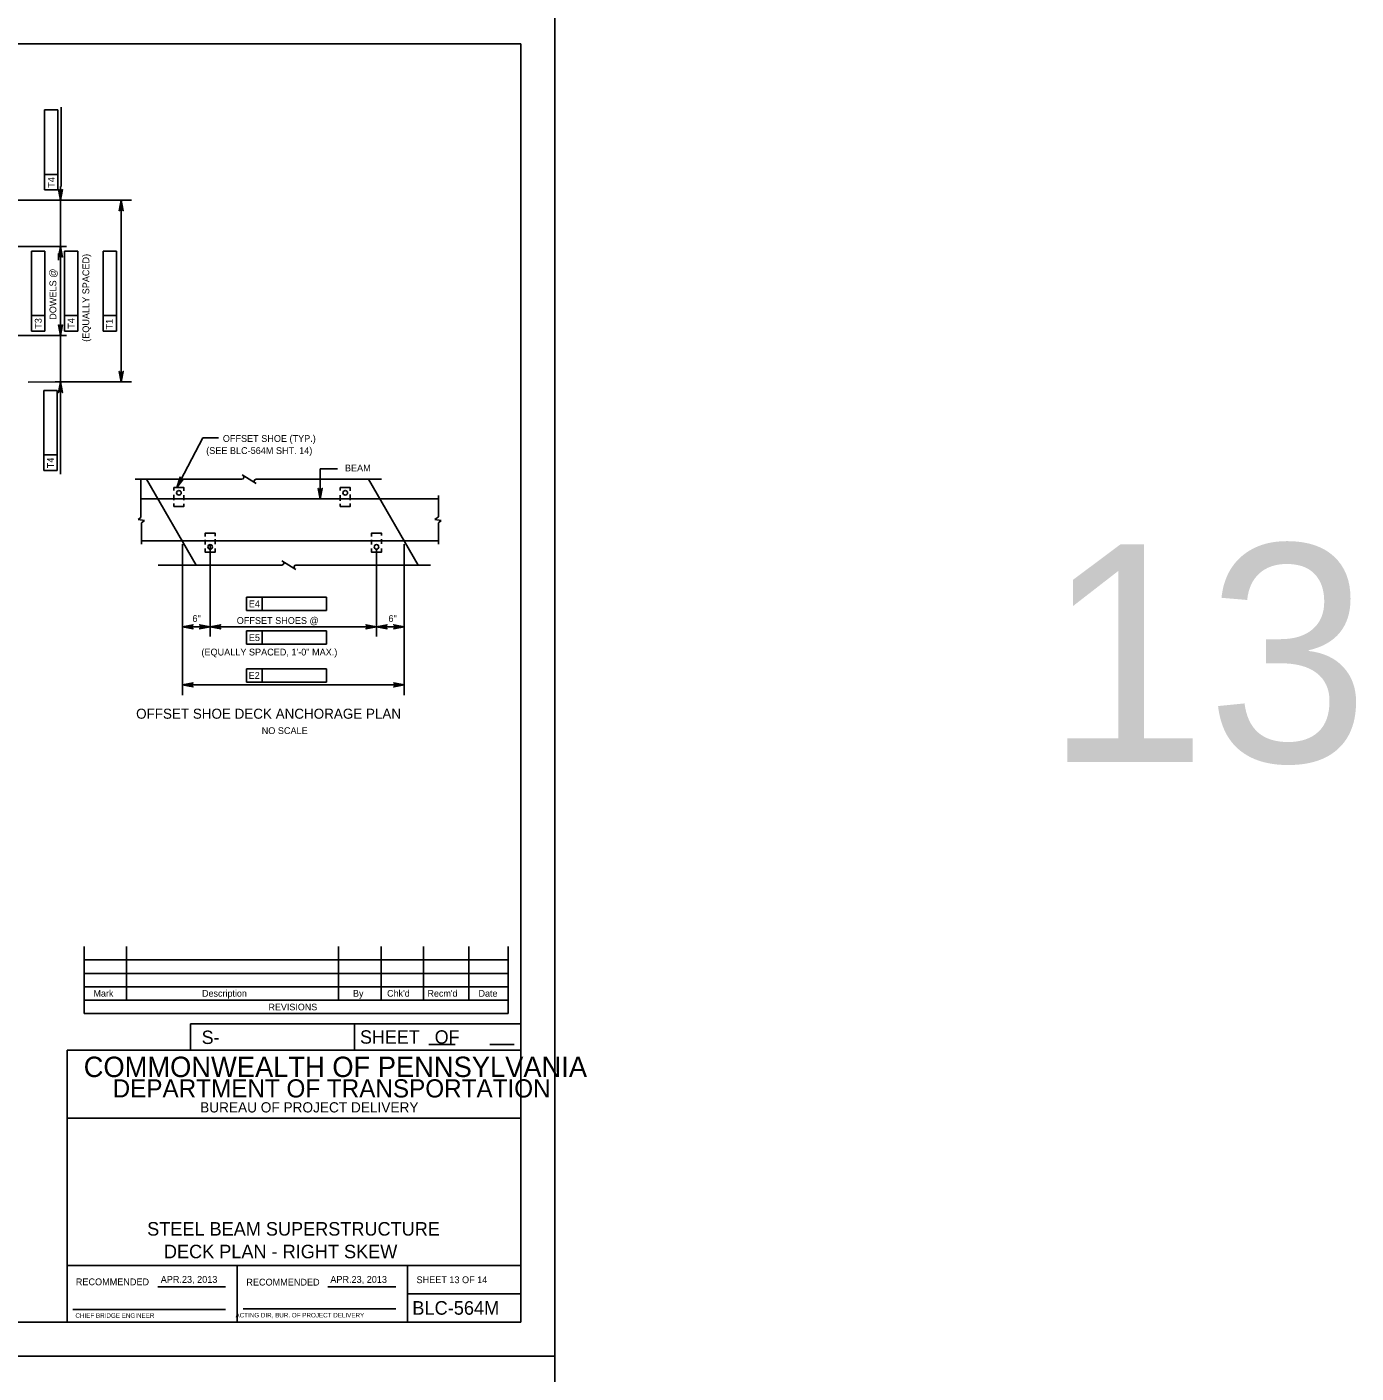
# Model space of a CAD drawing. Extents: x 638175 to 640495, y 294277 to 298435.
# Drawn here: x 639885 to 640471, y 294864 to 295458 of the extents above; entities that cross this region are included whole.
import ezdxf

# ---------------------------------------------------------------- set-up
doc = ezdxf.new("R2010")
doc.units = 0
for name, color, linetype in [('1', 7, 'Continuous'), ('2', 7, 'Continuous'), ('3', 7, 'Continuous'), ('4', 7, 'Continuous'), ('53', 7, 'Continuous'), ('PLT-BNDY', 7, 'Continuous')]:
    doc.layers.add(name, color=color, linetype=linetype)

msp = doc.modelspace()

# ---------------------------------------------------------------- linework, layer by layer
at = {"layer": '2'}
for p, q in [((639316.46, 295450.46), (640102.46, 295450.46)), ((640102.46, 295450.46), (640102.46, 294886.46)), ((639937.34, 295258.4), (639959.24, 295220.5)), ((640035.38, 295258.4), (640057.29, 295220.5)), ((639909.92, 295052.15), (639909.92, 295022.62)), ((639928.62, 295052.15), (639928.62, 295028.53)), ((640022.13, 295052.15), (640022.13, 295028.53)), ((640040.83, 295052.15), (640040.83, 295028.53)), ((640059.53, 295052.15), (640059.53, 295028.53)), ((640079.59, 295052.15), (640079.59, 295028.53)), ((640096.94, 295052.15), (640096.94, 295022.62)), ((640096.94, 295046.24), (639909.92, 295046.24)), ((640096.94, 295040.34), (639909.92, 295040.34)), ((640096.94, 295034.43), (639909.92, 295034.43)), ((640096.94, 295028.53), (639909.92, 295028.53)), ((640096.94, 295022.62), (639909.92, 295022.62)), ((640102.46, 295018.11), (639956.78, 295018.11)), ((639956.78, 295018.11), (639956.78, 295006.46)), ((640029.09, 295018.11), (640029.09, 295006.46)), ((640102.46, 295006.46), (639902.46, 295006.46)), ((639902.46, 295006.46), (639902.46, 294886.46)), ((640061.95, 295009), (640073.6, 295009)), ((640088.83, 295009), (640099.56, 295009)), ((640102.46, 294976.46), (639902.46, 294976.46)), ((640102.46, 294911.46), (639902.46, 294911.46)), ((639977.46, 294886.46), (639977.46, 294911.46)), ((640052.46, 294911.46), (640052.46, 294886.46)), ((639942.42, 294901.96), (639972.19, 294901.96)), ((640017.42, 294901.96), (640047.33, 294901.96)), ((640052.46, 294898.96), (640102.46, 294898.96)), ((639904.96, 294891.96), (639972.19, 294891.96)), ((639980.08, 294892.33), (640047.33, 294892.33)), ((640102.46, 294886.46), (639316.46, 294886.46))]:
    msp.add_line(p, q, dxfattribs=at)
at = {"layer": '3'}
for p, q in [((639720.78, 295361.01), (639902.09, 295361.04)), ((639741.66, 295321.77), (639902.09, 295321.8)), ((639962.21, 295276.64), (639969.2, 295276.64)), ((639979.57, 295260.33), (639985.73, 295256.46)), ((640014.03, 295263), (640021.57, 295263)), ((639979.5, 295258.4), (639932.35, 295258.4)), ((639934.87, 295241.52), (639934.87, 295258.34)), ((640041.04, 295258.4), (639985.71, 295258.4)), ((639934.87, 295249.67), (640066.17, 295249.67)), ((640066.17, 295241.8), (640066.17, 295251.17)), ((640064.63, 295240.61), (640066.17, 295241.8)), ((639933.7, 295240.61), (639934.87, 295241.52)), ((639936.46, 295240.18), (639933.7, 295240.61)), ((639935.24, 295239.09), (639936.46, 295240.18)), ((639935.24, 295229.67), (639935.24, 295239.09)), ((640067.39, 295240.18), (640064.63, 295240.61)), ((640066.17, 295239.09), (640067.39, 295240.18)), ((640066.17, 295229.67), (640066.17, 295239.09)), ((640066.17, 295231.21), (639935.24, 295231.21)), ((639953.26, 295229.73), (639953.26, 295189.02)), ((639965.49, 295229.73), (639965.49, 295189.02)), ((640038.86, 295227.65), (640038.86, 295189.02)), ((640051.09, 295229.73), (640051.09, 295189.02)), ((639942.57, 295220.5), (639997.06, 295220.5)), ((639997.13, 295222.43), (640003.29, 295218.56)), ((640003.27, 295220.5), (640062.64, 295220.5)), ((639968.32, 295193.27), (640036.03, 295193.27))]:
    msp.add_line(p, q, dxfattribs=at)
for points in [[(639953.93, 295253.27), (639953.93, 295254.66), (639949.47, 295254.66), (639949.47, 295253.34)], [(639950.85, 295254.78), (639952.22, 295259.32), (639952.28, 295258.89), (639952.47, 295258.58), (639952.72, 295258.39), (639953.02, 295258.29), (639953.39, 295258.31), (639953.77, 295258.52), (639950.85, 295254.78), (639953.39, 295258.31), (639953.02, 295258.29), (639950.85, 295254.78), (639952.72, 295258.39), (639952.47, 295258.58), (639950.85, 295254.78), (639952.28, 295258.89)], [(640014.02, 295249.67), (640013.15, 295254.33), (640013.4, 295253.97), (640013.71, 295253.78), (640014.02, 295253.73), (640014.34, 295253.78), (640014.65, 295253.97), (640014.9, 295254.33), (640014.02, 295249.67), (640014.65, 295253.97), (640014.34, 295253.78), (640014.02, 295249.67), (640014.02, 295253.73), (640013.71, 295253.78), (640014.02, 295249.67), (640013.4, 295253.97)], [(640022.82, 295253.34), (640022.82, 295254.66), (640027.29, 295254.66), (640027.29, 295253.27)], [(639949.47, 295251.51), (639949.47, 295249.07)], [(639953.93, 295249.07), (639953.93, 295251.28)], [(640022.82, 295248.84), (640022.82, 295251.28)], [(640027.29, 295251.59), (640027.29, 295249.14)], [(639949.47, 295247.61), (639949.47, 295246.35), (639953.93, 295246.35), (639953.93, 295247.46)], [(640027.29, 295247.61), (640027.29, 295246.35), (640022.82, 295246.35), (640022.82, 295247.46)], [(639963.25, 295233.09), (639963.25, 295234.53), (639967.72, 295234.53), (639967.72, 295233.32)], [(639963.25, 295229.5), (639963.25, 295231.64)], [(639967.72, 295231.95), (639967.72, 295229.65)], [(640041.08, 295233.48), (640041.08, 295234.53), (640036.61, 295234.53), (640036.61, 295233.17)], [(640036.61, 295231.64), (640036.61, 295229.5)], [(640041.08, 295229.81), (640041.08, 295231.87)], [(639967.72, 295227.82), (639967.72, 295226.21), (639963.25, 295226.21), (639963.25, 295227.82)], [(640036.61, 295227.82), (640036.61, 295226.21), (640041.08, 295226.21), (640041.08, 295227.82)], [(639953.26, 295193.27), (639957.92, 295194.14), (639957.56, 295193.89), (639957.38, 295193.58), (639957.32, 295193.27), (639957.38, 295192.96), (639957.56, 295192.64), (639957.92, 295192.4), (639953.26, 295193.27), (639957.56, 295192.64), (639957.38, 295192.96), (639953.26, 295193.27), (639957.32, 295193.27), (639957.38, 295193.58), (639953.26, 295193.27), (639957.56, 295193.89)], [(639965.49, 295193.27), (639960.83, 295192.4), (639961.19, 295192.64), (639961.37, 295192.96), (639961.43, 295193.27), (639961.37, 295193.58), (639961.19, 295193.89), (639960.83, 295194.14), (639965.49, 295193.27), (639961.19, 295193.89), (639961.37, 295193.58), (639965.49, 295193.27), (639961.43, 295193.27), (639961.37, 295192.96), (639965.49, 295193.27), (639961.19, 295192.64)], [(639965.49, 295193.27), (639970.15, 295194.14), (639969.79, 295193.89), (639969.61, 295193.58), (639969.55, 295193.27), (639969.61, 295192.96), (639969.79, 295192.64), (639970.15, 295192.4), (639965.49, 295193.27), (639969.79, 295192.64), (639969.61, 295192.96), (639965.49, 295193.27), (639969.55, 295193.27), (639969.61, 295193.58), (639965.49, 295193.27), (639969.79, 295193.89)], [(640038.86, 295193.27), (640034.2, 295192.4), (640034.56, 295192.64), (640034.75, 295192.96), (640034.8, 295193.27), (640034.75, 295193.58), (640034.56, 295193.89), (640034.2, 295194.14), (640038.86, 295193.27), (640034.56, 295193.89), (640034.75, 295193.58), (640038.86, 295193.27), (640034.8, 295193.27), (640034.75, 295192.96), (640038.86, 295193.27), (640034.56, 295192.64)], [(640038.86, 295193.27), (640043.52, 295194.14), (640043.17, 295193.89), (640042.98, 295193.58), (640042.93, 295193.27), (640042.98, 295192.96), (640043.17, 295192.64), (640043.52, 295192.4), (640038.86, 295193.27), (640043.17, 295192.64), (640042.98, 295192.96), (640038.86, 295193.27), (640042.93, 295193.27), (640042.98, 295193.58), (640038.86, 295193.27), (640043.17, 295193.89)], [(640051.09, 295193.27), (640046.43, 295192.4), (640046.79, 295192.64), (640046.98, 295192.96), (640047.03, 295193.27), (640046.98, 295193.58), (640046.79, 295193.89), (640046.43, 295194.14), (640051.09, 295193.27), (640046.79, 295193.89), (640046.98, 295193.58), (640051.09, 295193.27), (640047.03, 295193.27), (640046.98, 295192.96), (640051.09, 295193.27), (640046.79, 295192.64)], [(639953.26, 295167.61), (639957.92, 295168.48), (639957.56, 295168.23), (639957.38, 295167.92), (639957.32, 295167.61), (639957.38, 295167.3), (639957.56, 295166.98), (639957.92, 295166.74), (639953.26, 295167.61), (639957.56, 295166.98), (639957.38, 295167.3), (639953.26, 295167.61), (639957.32, 295167.61), (639957.38, 295167.92), (639953.26, 295167.61), (639957.56, 295168.23)], [(640051.09, 295167.61), (640046.43, 295166.74), (640046.79, 295166.98), (640046.98, 295167.3), (640047.03, 295167.61), (640046.98, 295167.92), (640046.79, 295168.23), (640046.43, 295168.48), (640051.09, 295167.61), (640046.79, 295168.23), (640046.98, 295167.92), (640051.09, 295167.61), (640047.03, 295167.61), (640046.98, 295167.3), (640051.09, 295167.61), (640046.79, 295166.98)]]:
    msp.add_lwpolyline(points, dxfattribs=at)
for points in [[(639956.09, 295193.74), (639956.09, 295192.8), (639953.26, 295193.27)], [(639962.65, 295193.74), (639962.65, 295192.8), (639965.49, 295193.27)], [(639968.32, 295193.74), (639968.32, 295192.8), (639965.49, 295193.27)], [(640036.03, 295193.74), (640036.03, 295192.8), (640038.86, 295193.27)], [(640041.7, 295193.74), (640041.7, 295192.8), (640038.86, 295193.27)], [(640048.26, 295193.74), (640048.26, 295192.8), (640051.09, 295193.27)]]:
    msp.add_lwpolyline(points, close=True, dxfattribs=at)
for centre in [(639951.7, 295252.38), (640025.06, 295252.38), (639965.49, 295228.49), (640038.84, 295228.49)]:
    msp.add_circle(centre, 1.02, dxfattribs=at)
for centre, start, end in [((639979.5, 295259.3), 270, 60), ((639985.8, 295257.49), 95.32859, 237.86724), ((639997.06, 295221.41), 270, 60), ((640003.36, 295219.59), 95.32859, 237.86724)]:
    msp.add_arc(centre, 0.909, start, end, dxfattribs=at)
at = {"layer": '4'}
for p, q in [((639892.45, 295421.31), (639898.36, 295421.31)), ((639892.45, 295392.9), (639892.45, 295421.31)), ((639898.36, 295421.31), (639898.36, 295386.01)), ((639899.74, 295387.54), (639899.74, 295422.62)), ((639892.45, 295386.01), (639892.45, 295392.9)), ((639898.36, 295392.9), (639892.45, 295392.9)), ((639898.36, 295386.01), (639892.45, 295386.01)), ((639899.48, 295361.03), (639899.48, 295387.54)), ((639829.73, 295381.52), (639930.77, 295381.52)), ((639901.03, 295381.54), (639903.98, 295381.54)), ((639926.27, 295301.28), (639926.27, 295381.52)), ((639899.48, 295321.79), (639899.48, 295361.03)), ((639899.67, 295361.03), (639902.09, 295361.03)), ((639899.67, 295361.03), (639901.89, 295361.03)), ((639886.67, 295323.77), (639886.67, 295359.07)), ((639886.67, 295359.07), (639892.58, 295359.07)), ((639892.58, 295359.07), (639892.58, 295323.77)), ((639898.62, 295358.03), (639898.62, 295355.03)), ((639901.21, 295359.07), (639907.11, 295359.07)), ((639901.21, 295330.66), (639901.21, 295359.07)), ((639907.11, 295359.07), (639907.11, 295323.77)), ((639918.29, 295359.07), (639924.19, 295359.07)), ((639918.29, 295330.66), (639918.29, 295359.07)), ((639924.19, 295359.07), (639924.19, 295323.77)), ((639892.58, 295330.66), (639886.67, 295330.66)), ((639899.48, 295324.79), (639899.48, 295327.79)), ((639901.21, 295323.77), (639901.21, 295330.66)), ((639907.11, 295330.66), (639901.21, 295330.66)), ((639918.29, 295323.77), (639918.29, 295330.66)), ((639924.19, 295330.66), (639918.29, 295330.66)), ((639892.58, 295323.77), (639886.67, 295323.77)), ((639899.48, 295321.8), (639899.48, 295260.59)), ((639899.66, 295321.8), (639901.68, 295321.8)), ((639907.11, 295323.77), (639901.21, 295323.77)), ((639924.19, 295323.77), (639918.29, 295323.77)), ((639904.16, 295301.28), (639885.19, 295301.27)), ((639897.13, 295301.28), (639930.77, 295301.28)), ((639898.12, 295301.28), (639903.98, 295301.28)), ((639892.08, 295262.25), (639892.08, 295297.55)), ((639892.08, 295297.55), (639897.98, 295297.55)), ((639897.98, 295297.55), (639897.98, 295262.25)), ((639897.98, 295269.14), (639892.08, 295269.14)), ((639897.98, 295262.25), (639892.08, 295262.25)), ((639981.53, 295206.35), (639981.53, 295200.44)), ((639988.42, 295206.35), (639981.53, 295206.35)), ((639988.42, 295200.44), (639988.42, 295206.35)), ((640016.83, 295206.35), (639988.42, 295206.35)), ((640016.83, 295206.35), (640016.83, 295200.44)), ((639953.26, 295201.95), (639953.26, 295163.11)), ((639981.53, 295200.44), (640016.83, 295200.44)), ((640051.09, 295201.95), (640051.09, 295163.11)), ((639955.08, 295193.27), (639963.3, 295193.27)), ((639981.53, 295191.45), (639981.53, 295185.54)), ((639988.42, 295191.45), (639981.53, 295191.45)), ((640016.83, 295191.45), (639988.42, 295191.45)), ((639988.42, 295185.54), (639988.42, 295191.45)), ((640016.83, 295191.45), (640016.83, 295185.54)), ((640040.02, 295193.27), (640048.24, 295193.27)), ((639981.53, 295185.54), (640016.83, 295185.54)), ((639981.49, 295174.76), (639988.38, 295174.76)), ((639981.49, 295168.86), (639981.49, 295174.76)), ((639988.38, 295168.86), (639988.38, 295174.76)), ((639988.38, 295174.76), (640016.79, 295174.76)), ((640016.79, 295174.76), (640016.79, 295168.86)), ((640048.09, 295167.61), (639956.26, 295167.61)), ((640016.79, 295168.86), (639981.49, 295168.86))]:
    msp.add_line(p, q, dxfattribs=at)
for points in [[(639899.48, 295381.52), (639900.35, 295386.18), (639900.11, 295385.82), (639899.79, 295385.64), (639899.48, 295385.59), (639899.17, 295385.64), (639898.86, 295385.82), (639898.61, 295386.18), (639899.48, 295381.52), (639898.86, 295385.82), (639899.17, 295385.64), (639899.48, 295381.52), (639899.48, 295385.59), (639899.79, 295385.64), (639899.48, 295381.52), (639900.11, 295385.82)], [(639926.27, 295381.52), (639925.4, 295376.86), (639925.65, 295377.22), (639925.96, 295377.41), (639926.27, 295377.46), (639926.59, 295377.41), (639926.9, 295377.22), (639927.15, 295376.86), (639926.27, 295381.52), (639926.9, 295377.22), (639926.59, 295377.41), (639926.27, 295381.52), (639926.27, 295377.46), (639925.96, 295377.41), (639926.27, 295381.52), (639925.65, 295377.22)], [(639899.48, 295361.03), (639898.61, 295356.37), (639898.86, 295356.73), (639899.17, 295356.92), (639899.48, 295356.97), (639899.79, 295356.92), (639900.11, 295356.73), (639900.35, 295356.37), (639899.48, 295361.03), (639900.11, 295356.73), (639899.79, 295356.92), (639899.48, 295361.03), (639899.48, 295356.97), (639899.17, 295356.92), (639899.48, 295361.03), (639898.86, 295356.73)], [(639899.48, 295321.8), (639900.35, 295326.46), (639900.11, 295326.1), (639899.79, 295325.92), (639899.48, 295325.86), (639899.17, 295325.92), (639898.86, 295326.1), (639898.61, 295326.46), (639899.48, 295321.8), (639898.86, 295326.1), (639899.17, 295325.92), (639899.48, 295321.8), (639899.48, 295325.86), (639899.79, 295325.92), (639899.48, 295321.8), (639900.11, 295326.1)], [(639899.48, 295301.28), (639898.61, 295296.62), (639898.86, 295296.98), (639899.17, 295297.16), (639899.48, 295297.22), (639899.79, 295297.16), (639900.11, 295296.98), (639900.35, 295296.62), (639899.48, 295301.28), (639900.11, 295296.98), (639899.79, 295297.16), (639899.48, 295301.28), (639899.48, 295297.22), (639899.17, 295297.16), (639899.48, 295301.28), (639898.86, 295296.98)], [(639926.27, 295301.28), (639927.15, 295305.94), (639926.9, 295305.58), (639926.59, 295305.39), (639926.27, 295305.34), (639925.96, 295305.39), (639925.65, 295305.58), (639925.4, 295305.94), (639926.27, 295301.28), (639925.65, 295305.58), (639925.96, 295305.39), (639926.27, 295301.28), (639926.27, 295305.34), (639926.59, 295305.39), (639926.27, 295301.28), (639926.9, 295305.58)], [(639950.85, 295254.78), (639962.21, 295276.64)], [(640014.02, 295249.67), (640014.02, 295263)]]:
    msp.add_lwpolyline(points, dxfattribs=at)
for points in [[(639899.98, 295358.03), (639898.98, 295358.03), (639899.48, 295361.03)], [(639950.85, 295254.78), (639950.93, 295254.87), (639950.88, 295254.9)], [(640014.02, 295249.67), (640014.05, 295249.78), (640014, 295249.78)], [(639956.26, 295168.11), (639956.26, 295167.11), (639953.26, 295167.61)], [(640048.09, 295168.11), (640048.09, 295167.11), (640051.09, 295167.61)]]:
    msp.add_lwpolyline(points, close=True, dxfattribs=at)
at = {"layer": 'PLT-BNDY'}
for points in [[(639276.46, 295465.46), (640117.46, 295465.46), (640117.46, 294871.46), (639276.46, 294871.46)], [(639276.46, 294871.46), (640117.46, 294871.46), (640117.46, 294277.46), (639276.46, 294277.46)]]:
    msp.add_lwpolyline(points, close=True, dxfattribs=at)

# ---------------------------------------------------------------- texts
at = {"layer": '1'}
msp.add_text('SHEET 13 OF 14', height=3, dxfattribs=at).set_placement((640056.5, 294903.63))
at = {"layer": '2'}
for s, height, p in [('Mark', 2.952, (639914.02, 295030.03)), ('Description', 2.9523, (639961.92, 295030.03)), ('By', 2.952, (640028.49, 295030.03)), ("Chk'd", 2.952, (640043.52, 295030.03)), ("Recm'd", 2.953, (640061.33, 295030.03)), ('Date', 2.952, (640083.86, 295030.03)), ('REVISIONS', 2.952, (639991.2, 295024.01)), ('S-', 5.905, (639961.73, 295009.17)), ('COMMONWEALTH OF PENNSYLVANIA', 9, (639909.71, 294994.58)), ('DEPARTMENT OF TRANSPORTATION', 8.0002, (639922.46, 294985.58)), ('BUREAU OF PROJECT DELIVERY', 4.5, (639961.05, 294978.96)), ('APR.23, 2013', 3, (639943.67, 294903.77)), ('APR.23, 2013', 3, (640018.48, 294903.77)), ('BLC-564M', 6, (640054.64, 294889.71)), ('CHIEF BRIDGE ENGINEER', 2.0002, (639906.05, 294888.33)), ('  ACTING DIR, BUR. OF PROJECT DELIVERY', 2.0002, (639975.11, 294888.51))]:
    msp.add_text(s, height=height, dxfattribs=at).set_placement(p)
for s, height, p in [('SHEET   OF', 5.907, (640031.58, 295009.31)), ('RECOMMENDED', 3, (639906.23, 294902.71)), ('RECOMMENDED', 3, (639981.44, 294902.58))]:
    msp.add_text(s, height=height, rotation=360, dxfattribs=at).set_placement(p)
at = {"layer": '3'}
msp.add_text('OFFSET SHOE (TYP.)', height=3, dxfattribs=at).set_placement((639971.06, 295274.85))
at = {"layer": '4'}
for s, p in [('T4', (639896.93, 295386.99)), ('(EQUALLY SPACED)', (639912.16, 295319.02)), ('DOWELS @', (639897.62, 295328.73)), ('T3', (639891.15, 295324.75)), ('T4', (639905.69, 295324.75)), ('T1', (639922.5, 295324.46)), ('T4', (639896.55, 295263.23))]:
    msp.add_text(s, height=3, rotation=90, dxfattribs=at).set_placement(p)
for s, height, p in [('(SEE BLC-564M SHT. 14)', 3, (639963.72, 295269.52)), ('BEAM', 3, (640024.92, 295261.82)), ('E4', 3, (639982.51, 295201.87)), ('6"', 3, (639957.67, 295195.4)), ('OFFSET SHOES @', 3, (639977.2, 295194.53)), ('6"', 3, (640044.11, 295195.4)), ('E5', 3, (639982.54, 295186.97)), ('(EQUALLY SPACED, 1\'-0" MAX.)', 3, (639961.63, 295180.6)), ('E2', 3, (639982.44, 295170.29)), ('OFFSET SHOE DECK ANCHORAGE PLAN', 4.4292, (639932.83, 295152.69)), ('NO SCALE', 3, (639988.2, 295145.92)), ('STEEL BEAM SUPERSTRUCTURE', 5.9714, (639937.69, 294924.61)), ('DECK PLAN - RIGHT SKEW', 5.9714, (639945.09, 294914.61))]:
    msp.add_text(s, height=height, dxfattribs=at).set_placement(p)
at = {"layer": '53'}
msp.add_text('13', height=96, dxfattribs=at).set_placement((640333.73, 295133.62))

doc.saveas('drawing.dxf')
